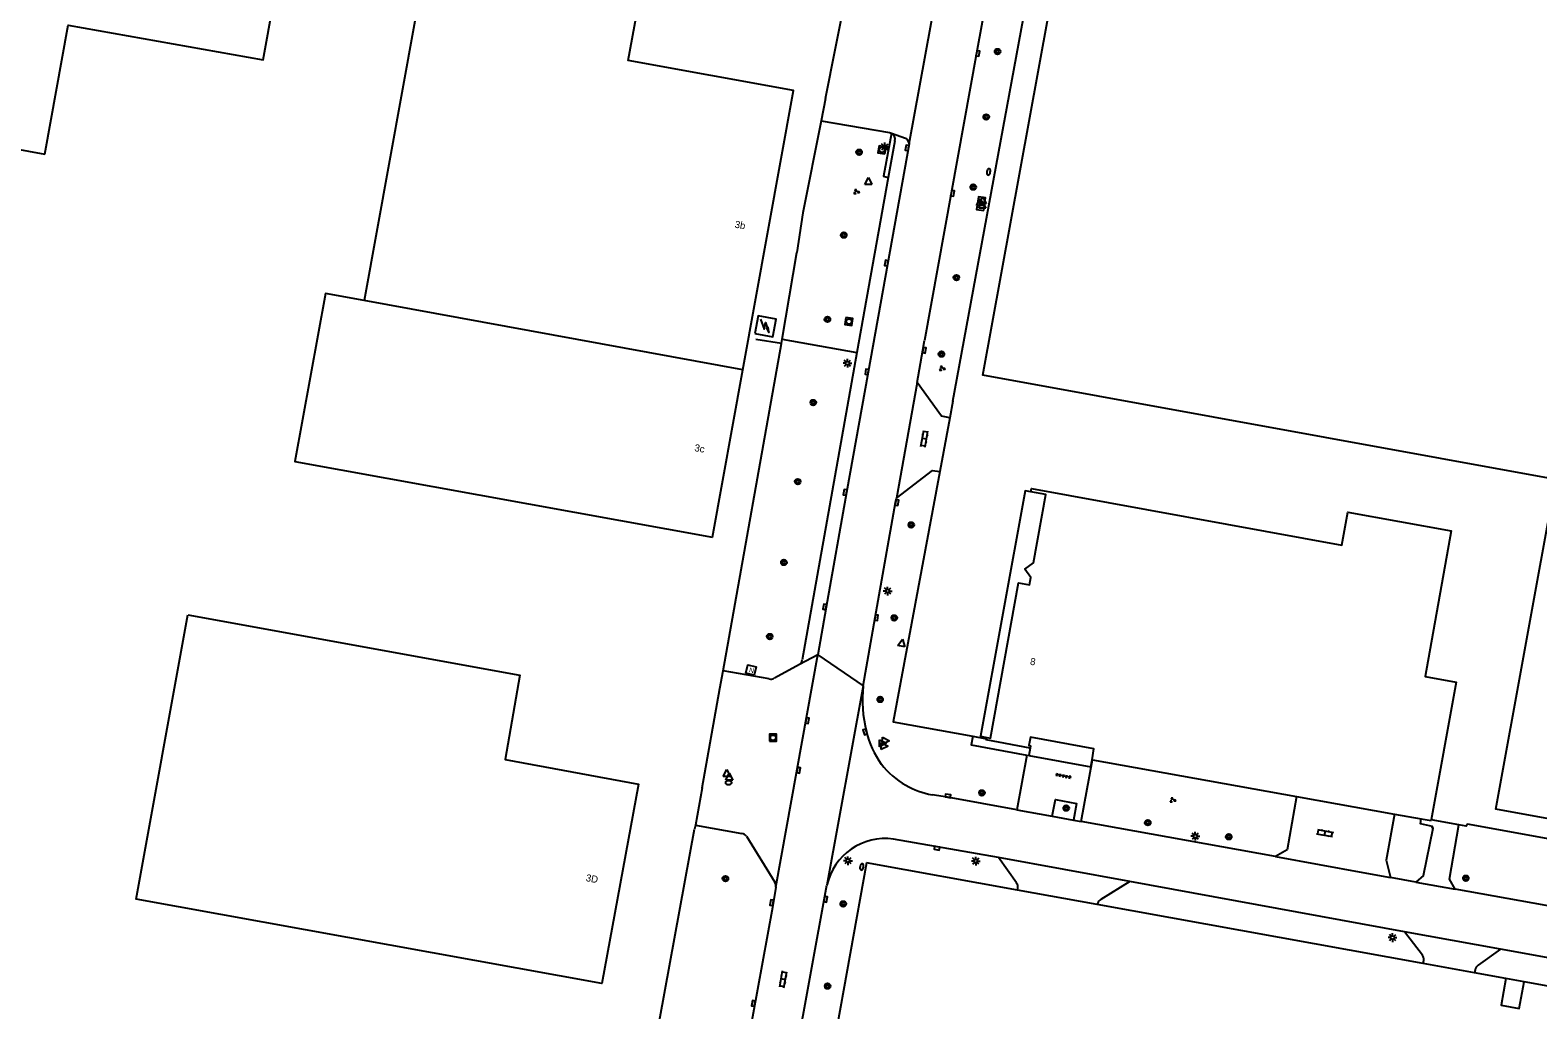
# Model space of a CAD drawing. Extents: x 130998 to 133001, y 398999 to 403002.
# Drawn here: x 132119.4 to 132332.6, y 399892.9 to 400031.5 of the extents above; entities that cross this region are included whole.
import ezdxf

# ---------------------------------------------------------------- set-up
doc = ezdxf.new("R2010")
doc.units = 0
for name, color, linetype in [('gg-afsc-hekwerk', 7, 'Continuous'), ('gg-anno-huisnummerreeks BGT', 7, 'Continuous'), ('gg-bbg-bijgebouw', 7, 'Continuous'), ('gg-bbg-hoofdgebouw', 7, 'Continuous'), ('gg-bbg-lage trafo', 7, 'Continuous'), ('gg-bbg-luifel en loopbrug', 7, 'Continuous'), ('gg-bbg-tussenscheiding', 7, 'Continuous'), ('gg-knt-verharding', 7, 'Continuous'), ('gg-knt-verharding nz', 7, 'Continuous'), ('gt-grn-groengrens', 7, 'Continuous'), ('gt-grn-weggrens', 7, 'Continuous'), ('gt-symb-boom', 7, 'Continuous'), ('gt-symb-brandkraan', 7, 'Continuous'), ('gt-symb-groenvak', 7, 'Continuous'), ('gt-symb-klinker verharding', 7, 'Continuous'), ('gt-symb-kolk', 7, 'Continuous'), ('gt-symb-lichtmast', 7, 'Continuous'), ('gt-symb-nortonput', 7, 'Continuous'), ('gt-symb-rioolschacht', 7, 'Continuous'), ('gt-symb-tegel verharding', 7, 'Continuous'), ('gt-symb-trafo symbool', 7, 'Continuous'), ('gt-symb-waterafsluiter', 7, 'Continuous')]:
    doc.layers.add(name, color=color, linetype=linetype)

# ---------------------------------------------------------------- blocks, each defined once
blk = doc.blocks.new('gt0-BOOM')
at = {"layer": 'gt-symb-boom'}
for radius in [0.4, 0.2]:
    blk.add_circle((0, 0), radius, dxfattribs=at)
blk = doc.blocks.new('gt0-LMAST')
at = {"layer": 'gt-symb-lichtmast'}
for p, q in [((-0.18, 0.17), (-0.45, 0.44)), ((-0.01, 0.25), (-0.01, 0.62)), ((0.17, 0.17), (0.44, 0.44)), ((-0.26, 0), (-0.63, 0)), ((-0.18, -0.18), (-0.45, -0.45)), ((-0.01, -0.25), (-0.01, -0.63)), ((0.44, -0.45), (0.17, -0.18)), ((0.24, 0), (0.62, 0))]:
    blk.add_line(p, q, dxfattribs=at)
blk.add_circle((-0.01, 0), 0.25, dxfattribs=at)
blk = doc.blocks.new('gt0-KL1')
at = {"layer": 'gt-symb-klinker verharding'}
for p, q in [((-1.15, 0.3), (1.15, 0.3)), ((-1, -0.3), (-1, 0.3)), ((-0.5, 0.3), (-0.5, 0.45)), ((0, -0.3), (0, 0.3)), ((0.5, 0.3), (0.5, 0.45)), ((1, -0.3), (1, 0.3)), ((-1.15, -0.3), (1.15, -0.3)), ((-0.5, -0.45), (-0.5, -0.3)), ((0.5, -0.45), (0.5, -0.3))]:
    blk.add_line(p, q, dxfattribs=at)
blk = doc.blocks.new('gt0-TEG1')
at = {"layer": 'gt-symb-tegel verharding'}
for p, q in [((-1.12, 0), (1.12, 0)), ((-0.9, -0.25), (-0.9, 0.25)), ((-0.45, -0.25), (-0.45, 0.25)), ((0, -0.25), (0, 0.25)), ((0.45, -0.25), (0.45, 0.25)), ((0.9, -0.25), (0.9, 0.25))]:
    blk.add_line(p, q, dxfattribs=at)
blk = doc.blocks.new('gt0-GRVAK')
at = {"layer": 'gt-symb-groenvak'}
for p, q in [((-0.11, 0.19), (-0.23, 0.24)), ((-0.18, 0.15), (0.09, 0.15)), ((-0.09, 0.21), (-0.16, 0.32)), ((-0.05, 0.21), (-0.05, 0.39)), ((0, 0.21), (0.06, 0.32)), ((0.01, 0.19), (0.13, 0.24)), ((0.26, -0.05), (0.2, 0.06)), ((0.3, -0.05), (0.3, 0.13)), ((0.35, -0.05), (0.41, 0.06)), ((-0.24, -0.23), (-0.36, -0.18)), ((-0.32, -0.26), (-0.05, -0.26)), ((-0.23, -0.21), (-0.29, -0.09)), ((-0.18, -0.2), (-0.18, -0.02)), ((-0.14, -0.21), (-0.07, -0.09)), ((-0.12, -0.23), (0, -0.18)), ((0.24, -0.07), (0.12, -0.02)), ((0.17, -0.11), (0.44, -0.11)), ((0.37, -0.07), (0.49, -0.02))]:
    blk.add_line(p, q, dxfattribs=at)
blk = doc.blocks.new('gt0-KOLK')
at = {"layer": 'gt-symb-kolk'}
blk.add_lwpolyline([(0, 0), (0.37, 0), (0.37, 0.4), (-0.38, 0.4), (-0.38, 0), (0, 0)], dxfattribs=at)
blk = doc.blocks.new('gt0-BR')
at = {"layer": 'gt-symb-brandkraan'}
for centre, radius, start, end in [((-0.24, 0), 0.206, 107.5669, 252.4331), ((0.6, -2.66), 3, 106.892, 107.5669), ((0, -0.69), 0.938, 73.108, 106.892), ((-0.6, -2.66), 3, 72.4331, 73.108), ((0.24, 0), 0.206, 287.567, 72.4331), ((0.6, 2.66), 3, 252.4331, 253.108), ((0, 0.69), 0.938, 253.108, 286.8921), ((-0.6, 2.66), 3, 286.8921, 287.567)]:
    blk.add_arc(centre, radius, start, end, dxfattribs=at)
blk = doc.blocks.new('gt0-WAFSL')
at = {"layer": 'gt-symb-waterafsluiter'}
for p, q in [((-0.5, -0.33), (0, 0.67)), ((0, 0.67), (0.5, -0.33)), ((0.5, -0.33), (-0.5, -0.33))]:
    blk.add_line(p, q, dxfattribs=at)
blk = doc.blocks.new('gt0-RS')
at = {"layer": 'gt-symb-rioolschacht'}
blk.add_lwpolyline([(-0.5, -0.5), (0.5, -0.5), (0.5, 0.5), (-0.5, 0.5)], close=True, dxfattribs=at)
blk.add_circle((0, 0), 0.375, dxfattribs=at)
blk = doc.blocks.new('gt0-HSP')
at = {"layer": 'gt-symb-trafo symbool'}
for points in [[(0.77, 0.75), (-0.53, 0), (0.47, 0), (-0.83, -0.75)], [(-0.22, -0.24), (-0.83, -0.75), (-0.08, -0.48)]]:
    blk.add_lwpolyline(points, dxfattribs=at)
blk = doc.blocks.new('gt0-NPUT')
at = {"layer": 'gt-symb-nortonput'}
blk.add_lwpolyline([(-0.57, -0.61), (-0.57, 0.59), (0.63, 0.59), (0.63, -0.61)], close=True, dxfattribs=at)
blk.add_text('N', height=0.7, dxfattribs=at).set_placement((-0.22, -0.38))

msp = doc.modelspace()

# ---------------------------------------------------------------- linework, layer by layer
at = {"layer": 'gg-afsc-hekwerk'}
for p, q in [((132231.86, 400021.79), (132235.67, 400041.07)), ((132231.86, 400021.79), (132231.24, 400018.61)), ((132225.71, 399987.74), (132227.8, 400000)), ((132217.37, 399940.85), (132225.61, 399987.13)), ((132225.61, 399987.13), (132221.99, 399987.71)), ((132225.61, 399987.13), (132225.71, 399987.74)), ((132249.86, 399978.97), (132249.43, 399976.64)), ((132249.43, 399976.64), (132248.01, 399969.02)), ((132216.92, 399938.34), (132217.37, 399940.85)), ((132214.42, 399924.27), (132216.92, 399938.34)), ((132252.68, 399931.58), (132254.6, 399931.23)), ((132214.42, 399924.27), (132213.45, 399919.02)), ((132200.17, 399846.78), (132213.34, 399918.42)), ((132213.45, 399919.02), (132213.34, 399918.42)), ((132321.41, 399919.06), (132317.5, 399919.75)), ((132237.65, 399913.69), (132220.57, 399818.85)), ((132258.98, 399909.82), (132237.65, 399913.69)), ((132270.28, 399907.77), (132258.98, 399909.82)), ((132316.35, 399899.42), (132270.28, 399907.77)), ((132323.62, 399898.1), (132316.35, 399899.42)), ((132328.05, 399897.3), (132323.62, 399898.1)), ((132476.16, 399870.45), (132330.61, 399896.83))]:
    msp.add_line(p, q, dxfattribs=at)
for points in [[(132249.86, 399978.97), (132268.5, 400080.36), (132279.92, 400143.83)], [(132231.24, 400018.61), (132228.67, 400005.63), (132227.8, 400000)], [(132248.01, 399969.02), (132241.44, 399933.62), (132252.68, 399931.58)], [(132448.45, 399896.27), (132322.62, 399919.14), (132322.41, 399918.88), (132321.41, 399919.06)]]:
    msp.add_lwpolyline(points, dxfattribs=at)
at = {"layer": 'gg-bbg-bijgebouw'}
msp.add_lwpolyline([(132221.85, 399988.57), (132224.4, 399988.09), (132224.87, 399990.59), (132222.32, 399991.07), (132221.85, 399988.57)], dxfattribs=at)
at = {"layer": 'gg-bbg-hoofdgebouw'}
for p, q in [((132215.88, 399959.74), (132220.17, 399983.41)), ((132254.64, 399931.41), (132254.6, 399931.23)), ((132269.62, 399928.24), (132269.53, 399928.26)), ((132269.62, 399928.24), (132298.43, 399923.07)), ((132298.43, 399923.07), (132312.31, 399920.58)), ((132312.31, 399920.58), (132316.08, 399919.9)), ((132316.08, 399919.9), (132317.48, 399919.65)), ((132317.5, 399919.75), (132317.48, 399919.65))]:
    msp.add_line(p, q, dxfattribs=at)
for points in [[(132449.84, 399936.08), (132446.54, 399936.68), (132440.05, 399900.63), (132326.64, 399921.26), (132335.09, 399967.92), (132254.1, 399982.64), (132275.19, 400098.51), (132309.87, 400092.22), (132315.55, 400123.48), (132312.29, 400124.07), (132316.85, 400149.19), (132320.07, 400148.6), (132322.4, 400161.56), (132467.07, 400135.32)], [(132121.5, 400013.93), (132124.79, 400032.18), (132152.35, 400027.26), (132156.53, 400050.45), (132085.48, 400063.28), (132078.04, 400021.89), (132121.5, 400013.93)], [(132220.17, 399983.41), (132227.33, 400022.93), (132203.97, 400027.17), (132205.73, 400036.91), (132175.53, 400042.38), (132166.63, 399993.21)], [(132166.63, 399993.21), (132161.15, 399994.2), (132156.84, 399970.44), (132215.88, 399959.74)], [(132254.64, 399931.41), (132255.16, 399931.31), (132259.15, 399953.29), (132260.71, 399953.01), (132260.88, 399954.04), (132260.03, 399955.24), (132261.25, 399956.11), (132262.98, 399965.79), (132260.9, 399966.17)], [(132260.9, 399966.17), (132260.98, 399966.61), (132304.84, 399958.6), (132305.68, 399963.29), (132320.31, 399960.63), (132316.61, 399940.03), (132320.99, 399939.24), (132317.5, 399919.75)], [(132141.71, 399948.78), (132188.64, 399940.22), (132186.56, 399928.29), (132205.42, 399924.82), (132200.21, 399896.61), (132134.38, 399908.55), (132141.71, 399948.78)], [(132260.79, 399929.92), (132254.58, 399931.06), (132254.6, 399931.23)], [(132269.53, 399928.26), (132269.81, 399929.82), (132260.81, 399931.46), (132260.59, 399930.26), (132260.84, 399930.22), (132260.79, 399929.92)]]:
    msp.add_lwpolyline(points, dxfattribs=at)
at = {"layer": 'gg-bbg-lage trafo'}
msp.add_line((132330.61, 399896.83), (132328.05, 399897.3), dxfattribs=at)
msp.add_lwpolyline([(132328.05, 399897.3), (132327.37, 399893.57), (132329.93, 399893.1), (132330.61, 399896.83)], dxfattribs=at)
at = {"layer": 'gg-bbg-luifel en loopbrug'}
for points in [[(132260.9, 399966.17), (132260.08, 399966.31), (132253.78, 399931.59), (132254.64, 399931.41)], [(132260.79, 399929.92), (132260.59, 399928.85), (132269.35, 399927.26), (132269.53, 399928.26)]]:
    msp.add_lwpolyline(points, dxfattribs=at)
at = {"layer": 'gg-bbg-tussenscheiding'}
msp.add_line((132220.17, 399983.41), (132166.63, 399993.21), dxfattribs=at)
at = {"layer": 'gg-knt-verharding'}
for p, q in [((132241.66, 400015.81), (132240.72, 400010.63)), ((132240.72, 400010.63), (132236.3, 399985.84)), ((132245.62, 399986.21), (132245.87, 399987.54)), ((132236.3, 399985.84), (132228.56, 399942.4)), ((132244.79, 399981.63), (132245.62, 399986.21)), ((132228.17, 399941.73), (132224.62, 399939.79)), ((132230.78, 399943.12), (132228.17, 399941.73)), ((132223.87, 399939.69), (132217.37, 399940.85)), ((132268, 399919.53), (132269.62, 399928.24)), ((132258.89, 399921.18), (132263.9, 399920.28)), ((132263.9, 399920.28), (132266.91, 399919.73)), ((132213.45, 399919.02), (132220.03, 399917.84)), ((132266.91, 399919.73), (132268, 399919.53)), ((132295.45, 399914.56), (132268, 399919.53)), ((132220.66, 399917.43), (132224.67, 399910.96)), ((132256.3, 399914.42), (132241.46, 399917.05)), ((132258.85, 399910.84), (132256.3, 399914.42)), ((132316.38, 399911.89), (132315.29, 399910.97)), ((132224.83, 399910.24), (132224.34, 399907.38)), ((132258.98, 399909.82), (132259.04, 399910.11)), ((132274.88, 399911.04), (132270.76, 399908.5)), ((132313.7, 399903.92), (132274.88, 399911.04)), ((132315.29, 399910.97), (132311.73, 399911.62)), ((132362.65, 399902.4), (132320.86, 399909.95)), ((132224.34, 399907.38), (132213.86, 399850.1)), ((132270.31, 399907.93), (132270.28, 399907.77)), ((132316.25, 399900.63), (132313.7, 399903.92)), ((132327.28, 399901.45), (132324.12, 399899.2)), ((132472.88, 399875.09), (132327.28, 399901.45)), ((132316.35, 399899.42), (132316.44, 399899.9)), ((132323.7, 399898.53), (132323.62, 399898.1))]:
    msp.add_line(p, q, dxfattribs=at)
for points in [[(132268.98, 400115.16), (132259.59, 400063.07), (132255.79, 400042.44), (132253.19, 400028.19), (132249.61, 400008.4), (132245.87, 399987.54)], [(132231.24, 400018.61), (132240.9, 400016.98), (132241.05, 400016.95), (132241.2, 400016.88)], [(132241.2, 400016.88), (132240.07, 400010.78), (132240.72, 400010.63)], [(132241.2, 400016.88), (132243.15, 400016.17), (132243.39, 400015.97), (132243.7, 400015.39)], [(132243.7, 400015.39), (132237.9, 399983.09), (132234.83, 399966.05), (132231.94, 399949.85), (132230.78, 399943.12)], [(132254.22, 400005.96), (132254.47, 400007.73), (132253.46, 400007.87), (132253.2, 400006.1), (132254.22, 400005.96)], [(132249.43, 399976.64), (132248.27, 399976.87), (132244.79, 399981.63)], [(132241.91, 399965.28), (132246.97, 399969.19), (132248.01, 399969.02)], [(132237.18, 399938.72), (132238.86, 399948.39), (132241.77, 399964.65), (132241.91, 399965.28)], [(132252.68, 399931.58), (132252.46, 399930.36), (132260.31, 399928.9), (132258.89, 399921.18)], [(132258.89, 399921.18), (132249.12, 399922.95), (132246.91, 399923.31)], [(132263.9, 399920.28), (132264.37, 399922.63), (132267.32, 399922.08), (132266.91, 399919.73)], [(132298.43, 399923.07), (132297.11, 399915.5), (132295.45, 399914.56)], [(132312.31, 399920.58), (132311.14, 399914.07), (132311.73, 399911.62)], [(132316.38, 399911.89), (132317.74, 399918.59), (132317.62, 399918.62), (132317.68, 399918.84), (132315.96, 399919.19), (132316.08, 399919.9)], [(132320.86, 399909.95), (132320.05, 399911.39), (132321.41, 399919.06)], [(132217.87, 399832.95), (132220.77, 399848.56), (132222.97, 399860.84), (132232.06, 399910.51)]]:
    msp.add_lwpolyline(points, dxfattribs=at)
for centre, radius, start, end in [((132240.74, 400016.05), 0.953, 345.7145, 61.4545), ((132227.66, 399942.47), 0.904, 304.1197, 355.4096), ((132224.11, 399940.76), 1.1, 256.8934, 297.3379), ((132255.06, 399936.69), 17.99, 173.5405, 194.311), ((132249.86, 399935.09), 12.56, 193.0679, 216.3513), ((132248.96, 399934.82), 11.68, 217.9299, 240.4865), ((132248.71, 399934.04), 10.88, 239.597, 260.4839), ((132219.84, 399916.84), 1.02, 35.9449, 79.3), ((132240.31, 399908.68), 8.45, 82.1579, 167.49), ((132223.84, 399910.4), 1, 350.9378, 34.2038), ((132258.19, 399910.28), 0.865, 349.0684, 40.3408), ((132271.35, 399907.57), 1.1, 122.2189, 160.8049), ((132315.31, 399900), 1.13, 354.6579, 33.4515), ((132324.62, 399898.41), 0.936, 122.3198, 172.2707)]:
    msp.add_arc(centre, radius, start, end, dxfattribs=at)
at = {"layer": 'gg-knt-verharding nz'}
for p, q in [((132243.7, 400015.39), (132248.68, 400042.71)), ((132244.79, 399981.63), (132241.91, 399965.28)), ((132224.83, 399910.24), (132230.78, 399943.12)), ((132274.88, 399911.04), (132256.3, 399914.42)), ((132295.45, 399914.56), (132307.8, 399912.33)), ((132307.8, 399912.33), (132311.73, 399911.62)), ((132315.29, 399910.97), (132320.86, 399909.95)), ((132327.28, 399901.45), (132313.7, 399903.92))]:
    msp.add_line(p, q, dxfattribs=at)
at = {"layer": 'gt-grn-groengrens'}
msp.add_line((132225.71, 399987.74), (132236.3, 399985.84), dxfattribs=at)
at = {"layer": 'gt-grn-weggrens'}
for p, q in [((132230.78, 399943.12), (132237.18, 399938.72)), ((132237.18, 399938.72), (132232.06, 399910.51))]:
    msp.add_line(p, q, dxfattribs=at)

# ---------------------------------------------------------------- block references
at = {"layer": 'gt-symb-boom'}
for p in [(132256.17, 400028.43), (132254.57, 400019.17), (132236.6, 400014.19), (132252.73, 400009.25), (132234.44, 400002.47), (132250.35, 399996.45), (132232.13, 399990.55), (132248.24, 399985.63), (132230.13, 399978.78), (132227.92, 399967.6), (132243.98, 399961.48), (132225.97, 399956.17), (132241.58, 399948.32), (132223.96, 399945.68), (132239.58, 399936.79), (132253.97, 399923.57), (132265.89, 399921.42), (132277.42, 399919.36), (132288.87, 399917.36), (132217.7, 399911.45), (132234.35, 399907.87), (132232.15, 399896.24)]:
    msp.add_blockref('gt0-BOOM', p, dxfattribs=at)
at = {"layer": 'gt-symb-boom', "rotation": 90}
msp.add_blockref('gt0-BOOM', (132322.38, 399911.51), dxfattribs=at)
at = {"layer": 'gt-symb-brandkraan'}
for p, rotation in [((132254.91, 400011.4), -101.07387115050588), ((132236.98, 399913.1), 78.81367070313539)]:
    msp.add_blockref('gt0-BR', p, dxfattribs=dict(at, rotation=rotation))
msp.add_blockref('gt0-BR', (132218.14, 399925.02), dxfattribs=at)
at = {"layer": 'gt-symb-groenvak'}
for p in [(132236.2, 400008.6), (132248.31, 399983.61), (132280.92, 399922.56)]:
    msp.add_blockref('gt0-GRVAK', p, dxfattribs=at)
at = {"layer": 'gt-symb-klinker verharding'}
for p, rotation in [((132245.84, 399973.66), 79.80279442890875), ((132302.47, 399917.89), -10.253598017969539), ((132225.88, 399897.2), 79.63367739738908)]:
    msp.add_blockref('gt0-KL1', p, dxfattribs=dict(at, rotation=rotation))
at = {"layer": 'gt-symb-kolk'}
for p, rotation in [((132253.19, 400028.19), -100.00096759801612), ((132243.59, 400014.77), 79.99903240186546), ((132249.61, 400008.4), -100.00096759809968), ((132240.67, 399998.48), 79.99903240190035), ((132245.62, 399986.21), -100.30997039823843), ((132237.9, 399983.09), 79.99903240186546), ((132234.83, 399966.05), 79.99903240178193), ((132241.77, 399964.65), -100.1407931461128), ((132231.94, 399949.85), 79.99903240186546), ((132238.86, 399948.39), -99.79214624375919), ((132229.08, 399933.82), -99.91074480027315), ((132237.63, 399932.25), 105.6069304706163), ((132227.86, 399926.82), -100.3445424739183), ((132249.12, 399922.95), -10.253598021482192), ((132247.63, 399915.95), 169.85920685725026), ((132224.46, 399908.02), 80.55652508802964), ((132231.68, 399908.56), -100.36632260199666), ((132221.84, 399893.77), 79.56697526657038)]:
    msp.add_blockref('gt0-KOLK', p, dxfattribs=dict(at, rotation=rotation))
at = {"layer": 'gt-symb-lichtmast'}
for p in [(132240.24, 400014.93), (132234.96, 399984.35), (132240.64, 399952.12), (132284.14, 399917.46), (132235.03, 399913.98), (132253.1, 399913.93), (132312.02, 399903.11)]:
    msp.add_blockref('gt0-LMAST', p, dxfattribs=at)
at = {"layer": 'gt-symb-nortonput', "rotation": -13.063337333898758}
msp.add_blockref('gt0-NPUT', (132221.29, 399940.97), dxfattribs=at)
at = {"layer": 'gt-symb-rioolschacht'}
for p, rotation in [((132239.84, 400014.52), 79.69002960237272), ((132235.16, 399990.23), -97.81418085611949)]:
    msp.add_blockref('gt0-RS', p, dxfattribs=dict(at, rotation=rotation))
msp.add_blockref('gt0-RS', (132224.44, 399931.38), dxfattribs=at)
at = {"layer": 'gt-symb-tegel verharding', "rotation": -11.00666417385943}
msp.add_blockref('gt0-TEG1', (132265.49, 399925.99), dxfattribs=at)
at = {"layer": 'gt-symb-trafo symbool', "rotation": 79.2853561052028}
msp.add_blockref('gt0-HSP', (132223.27, 399989.66), dxfattribs=at)
at = {"layer": 'gt-symb-waterafsluiter'}
for p in [(132237.92, 400009.94), (132253.7, 400006.99), (132254.08, 400007.23), (132254.01, 400006.59), (132217.89, 399926.22), (132218.24, 399925.69)]:
    msp.add_blockref('gt0-WAFSL', p, dxfattribs=at)
for p, rotation in [((132242.63, 399944.65), -10.30997039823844), ((132239.8, 399930.6), -90.00000000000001), ((132240.24, 399930.95), -90.00000000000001), ((132240.06, 399930.19), -90.00000000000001)]:
    msp.add_blockref('gt0-WAFSL', p, dxfattribs=dict(at, rotation=rotation))

# ---------------------------------------------------------------- texts
at = {"layer": 'gg-anno-huisnummerreeks BGT'}
for s, rotation, p in [('3b', 349.7, (132218.96, 400003.53)), ('3c', 349.7, (132213.27, 399971.93)), ('8', 349.7, (132260.72, 399941.72)), ('3D', 349.5, (132197.91, 399911.11))]:
    msp.add_text(s, height=1, rotation=rotation, dxfattribs=at).set_placement(p)

doc.saveas('drawing.dxf')
